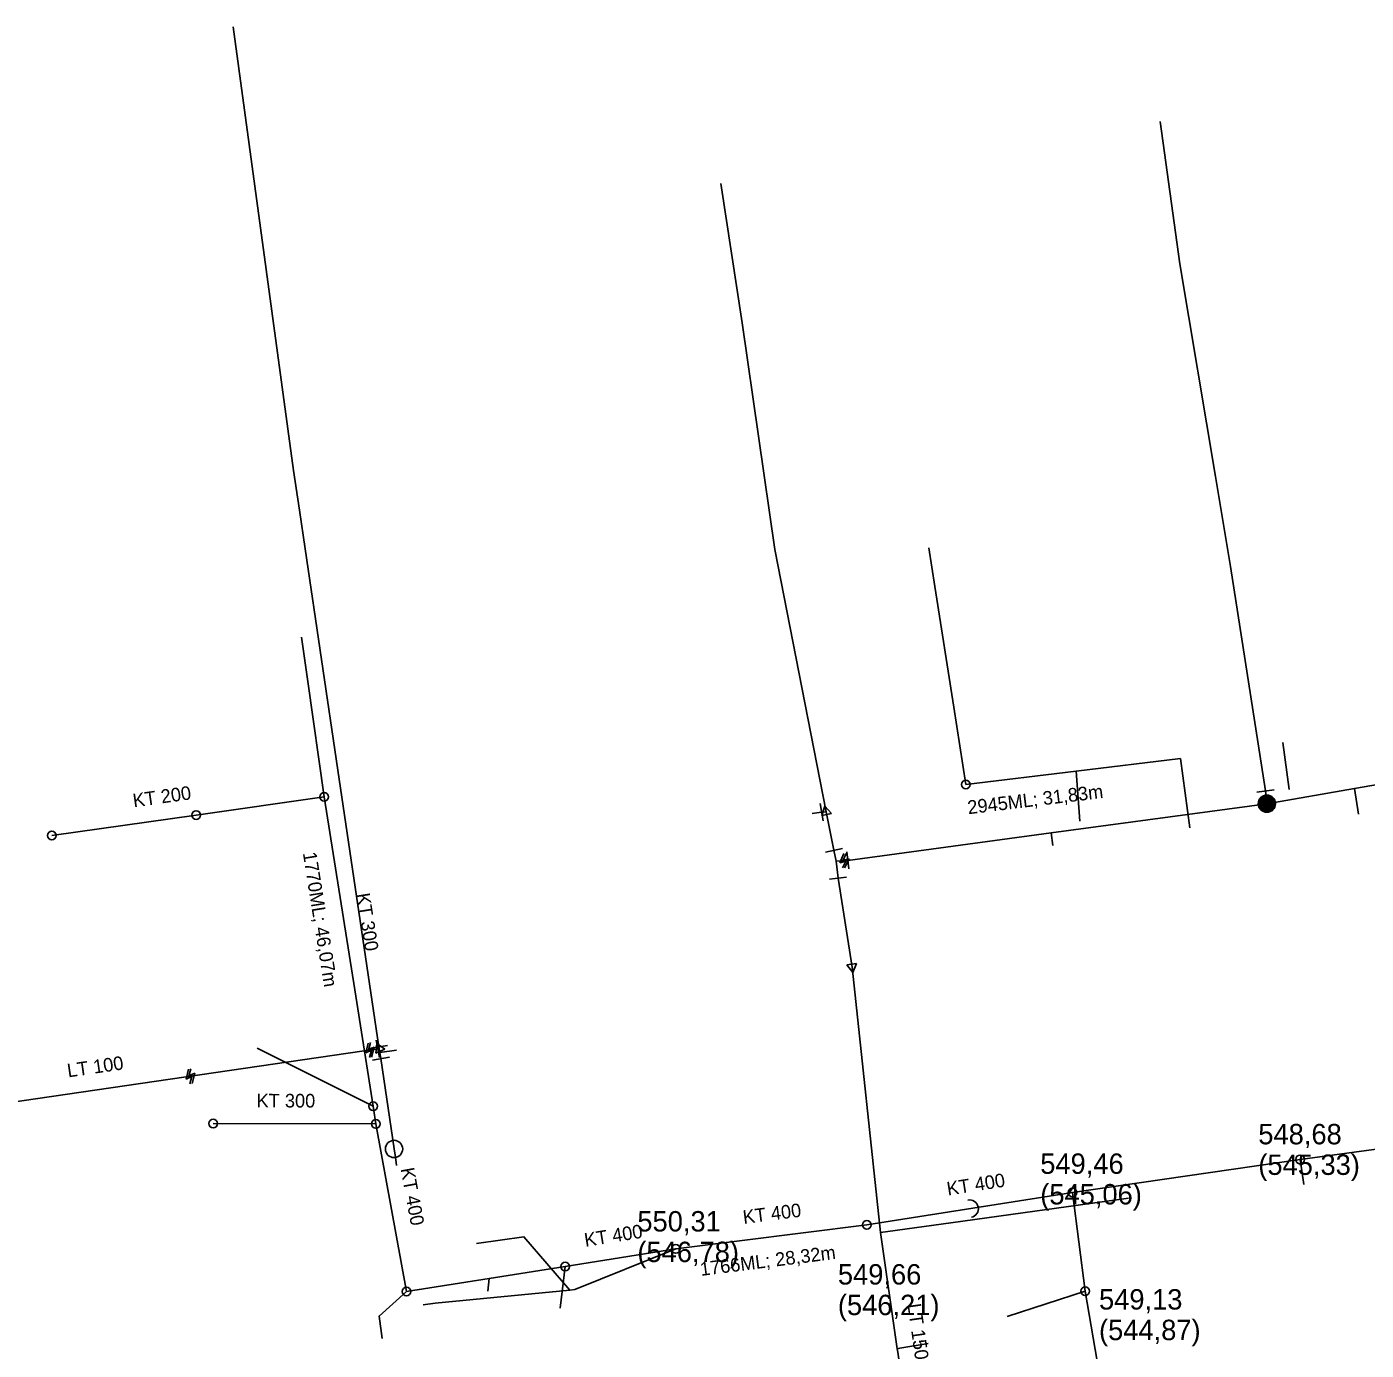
# Model space of a CAD drawing. Extents: x -867696 to -865033, y -1042522 to -1039817.
# Drawn here: x -866337.2 to -866140.2, y -1040061.2 to -1039866.6 of the extents above; entities that cross this region are included whole.
import ezdxf

# ---------------------------------------------------------------- set-up
doc = ezdxf.new("R2010")
doc.units = 0
for name, color, linetype in [('KN - jednotna', 7, 'Continuous'), ('KN - ostatni', 7, 'Continuous'), ('KN - popis material', 7, 'Continuous'), ('KN - popis ostatni', 7, 'Continuous'), ('KN - popis usek delka', 7, 'Continuous'), ('KN - pripojka', 7, 'Continuous'), ('KN - sachta komora', 7, 'Continuous'), ('Level 1', 7, 'Continuous'), ('V - armatura', 7, 'Continuous'), ('V - hydrant', 7, 'Continuous'), ('V - ostatni', 7, 'Continuous'), ('V - popis material', 7, 'Continuous'), ('V - pripojka', 7, 'Continuous'), ('V - rozvadeci', 7, 'Continuous'), ('V - sachta', 7, 'Continuous')]:
    doc.layers.add(name, color=color, linetype=linetype)

# ---------------------------------------------------------------- blocks, each defined once
blk = doc.blocks.new('100.M')
at = {"layer": 'Level 1'}
blk.add_circle((0, 0), 1.27, dxfattribs=at)
blk = doc.blocks.new('107')
at = {"layer": 'Level 1'}
blk.add_arc((0, 0), 1.27, 270, 90, dxfattribs=at)
blk = doc.blocks.new('111')
at = {"layer": 'Level 1'}
for p, q in [((0.42, 0.72), (-0.83, 0)), ((-0.83, 0), (0.42, -0.72)), ((0.42, -0.72), (0.42, 0.72))]:
    blk.add_line(p, q, dxfattribs=at)
blk = doc.blocks.new('147')
at = {"layer": 'Level 1'}
blk.add_line((0, 1.27), (0, -1.27), dxfattribs=at)
blk = doc.blocks.new('160')
at = {"layer": 'Level 1'}
for p, q in [((-1.26, -0.04), (0.05, 1.27)), ((-1.26, -0.06), (0.06, 1.27)), ((-1.26, -0.07), (0.08, 1.27)), ((-1.26, -0.09), (0.09, 1.27)), ((-1.26, 0.11), (-0.12, 1.26)), ((-1.26, 0.1), (-0.1, 1.26)), ((-1.26, 0.08), (-0.09, 1.26)), ((-1.26, 0.07), (-0.07, 1.26)), ((-1.26, 0.06), (-0.06, 1.26)), ((-1.26, 0.04), (-0.04, 1.26)), ((-1.26, 0.03), (-0.03, 1.26)), ((-1.26, 0.01), (-0.01, 1.26)), ((-1.26, 0), (0, 1.26)), ((-1.26, -0.02), (0.02, 1.26)), ((-1.26, -0.03), (0.03, 1.26)), ((-1.26, -0.1), (0.1, 1.26)), ((-1.26, -0.11), (0.12, 1.26)), ((-1.26, -0.13), (0.13, 1.26)), ((-1.26, -0.14), (0.14, 1.26)), ((-1.26, 0.17), (-0.18, 1.25)), ((-1.26, 0.15), (-0.16, 1.25)), ((-1.26, 0.14), (-0.15, 1.25)), ((-1.26, 0.13), (-0.13, 1.25)), ((-1.26, -0.16), (0.15, 1.25)), ((-1.26, -0.17), (0.16, 1.25)), ((-1.25, 0.21), (-0.21, 1.25)), ((-1.25, 0.19), (-0.19, 1.25)), ((-1.25, -0.18), (0.17, 1.25)), ((-1.25, -0.19), (0.19, 1.25)), ((-1.25, -0.2), (0.2, 1.24)), ((-1.25, -0.21), (0.21, 1.24)), ((-1.24, 0.25), (-0.24, 1.25)), ((-1.24, 0.23), (-0.22, 1.25)), ((-1.24, -0.22), (0.22, 1.24)), ((-1.24, -0.24), (0.23, 1.24)), ((-1.24, -0.25), (0.25, 1.24)), ((-1.23, 0.27), (-0.26, 1.24)), ((-1.23, 0.29), (-0.28, 1.23)), ((-1.23, -0.26), (0.26, 1.23)), ((-1.23, -0.27), (0.27, 1.23)), ((-1.23, -0.28), (0.28, 1.23)), ((-1.23, -0.29), (0.29, 1.23)), ((-1.22, 0.3), (-0.3, 1.23)), ((-1.22, 0.32), (-0.32, 1.22)), ((-1.22, -0.3), (0.31, 1.22)), ((-1.22, -0.32), (0.32, 1.22)), ((-1.22, -0.33), (0.33, 1.22)), ((-1.21, -0.34), (0.34, 1.22)), ((-1.21, -0.35), (0.35, 1.22)), ((-1.21, 0.36), (-0.36, 1.21)), ((-1.21, 0.34), (-0.34, 1.21)), ((-1.21, -0.36), (0.36, 1.21)), ((-1.21, -0.37), (0.38, 1.21)), ((-1.2, -0.38), (0.39, 1.21)), ((-1.2, 0.38), (-0.38, 1.2)), ((-1.2, -0.39), (0.4, 1.2)), ((-1.2, -0.41), (0.41, 1.2)), ((-1.2, 0.4), (-0.4, 1.19)), ((-1.19, -0.42), (0.42, 1.2)), ((-1.19, 0.42), (-0.43, 1.19)), ((-1.19, -0.43), (0.43, 1.19)), ((-1.19, -0.44), (0.44, 1.19)), ((-1.19, 0.44), (-0.45, 1.18)), ((-1.19, -0.45), (0.45, 1.18)), ((-1.18, -0.46), (0.46, 1.18)), ((-1.18, 0.46), (-0.47, 1.17)), ((-1.18, -0.47), (0.47, 1.17)), ((-1.17, 0.48), (-0.49, 1.17)), ((-1.17, -0.48), (0.48, 1.17)), ((-1.17, -0.49), (0.49, 1.16)), ((-1.16, 0.51), (-0.51, 1.16)), ((-1.16, -0.5), (0.5, 1.16)), ((-1.16, -0.51), (0.5, 1.16)), ((-1.15, -0.52), (0.51, 1.15)), ((-1.15, -0.53), (0.52, 1.15)), ((-1.14, 0.54), (-0.53, 1.15)), ((-1.14, -0.54), (0.53, 1.14)), ((-1.14, -0.54), (0.54, 1.14)), ((-1.13, -0.55), (0.55, 1.13)), ((-1.13, -0.56), (0.56, 1.13)), ((-1.12, 0.58), (-0.56, 1.14)), ((-1.12, -0.57), (0.57, 1.12)), ((-1.12, -0.58), (0.58, 1.12)), ((-1.11, -0.59), (0.59, 1.11)), ((-1.11, -0.6), (0.6, 1.11)), ((-1.1, 0.61), (-0.6, 1.11)), ((-1.1, -0.61), (0.61, 1.11)), ((-1.1, -0.62), (0.62, 1.1)), ((-1.09, -0.63), (0.63, 1.1)), ((-1.09, 0.64), (-0.64, 1.09)), ((-1.09, -0.64), (0.64, 1.09)), ((-1.08, -0.65), (0.65, 1.09)), ((-1.08, -0.65), (0.66, 1.08)), ((-1.07, -0.66), (0.67, 1.08)), ((-1.07, -0.67), (0.68, 1.07)), ((-1.07, 0.67), (-0.68, 1.06)), ((-1.06, -0.68), (0.69, 1.07)), ((-1.06, -0.69), (0.69, 1.06)), ((-1.05, -0.7), (0.7, 1.05)), ((-1.05, -0.71), (0.71, 1.05)), ((-1.05, 0.7), (-0.71, 1.04)), ((-1.04, -0.72), (0.72, 1.04)), ((-1.04, -0.73), (0.72, 1.04)), ((-1.03, -0.74), (0.73, 1.03)), ((-1.03, -0.75), (0.74, 1.02)), ((-1.03, 0.73), (-0.75, 1.01)), ((-1.02, -0.75), (0.75, 1.02)), ((-1.01, -0.76), (0.76, 1.01)), ((-1.01, -0.77), (0.76, 1)), ((-1, -0.77), (0.77, 1)), ((-0.99, -0.78), (0.78, 0.99)), ((-0.99, -0.79), (0.79, 0.98)), ((-0.98, -0.8), (0.79, 0.98)), ((-0.97, -0.8), (0.8, 0.97)), ((-0.97, -0.81), (0.81, 0.97)), ((-0.96, -0.82), (0.82, 0.96)), ((-0.95, -0.83), (0.83, 0.95)), ((-0.95, -0.83), (0.83, 0.95)), ((-0.94, -0.84), (0.84, 0.94)), ((-0.93, -0.85), (0.85, 0.93)), ((-0.93, -0.86), (0.86, 0.93)), ((-0.92, -0.86), (0.86, 0.92)), ((-0.91, 0.87), (-0.79, 0.99)), ((-0.91, -0.87), (0.87, 0.91)), ((-0.91, -0.88), (0.88, 0.91)), ((-0.9, -0.88), (0.89, 0.9)), ((-0.89, -0.89), (0.89, 0.89)), ((-0.88, -0.9), (0.9, 0.89)), ((-0.88, -0.91), (0.91, 0.88)), ((-0.87, -0.91), (0.92, 0.88)), ((-0.86, -0.92), (0.93, 0.87)), ((-0.86, -0.93), (0.93, 0.86)), ((-0.85, -0.94), (0.94, 0.85)), ((-0.84, -0.94), (0.94, 0.84)), ((-0.84, -0.95), (0.95, 0.84)), ((-0.83, -0.96), (0.96, 0.83)), ((-0.82, -0.96), (0.96, 0.82)), ((-0.82, -0.97), (0.97, 0.81)), ((-0.81, -0.98), (0.97, 0.8)), ((-0.8, -0.98), (0.98, 0.8)), ((-0.79, -0.99), (0.99, 0.79)), ((-0.78, -1), (0.99, 0.78)), ((-0.77, -1), (1, 0.77)), ((-0.77, -1.01), (1, 0.76)), ((-0.76, -1.01), (1.01, 0.75)), ((-0.75, -1.02), (1.02, 0.75)), ((-0.74, -1.02), (1.02, 0.74)), ((-0.73, -1.03), (1.03, 0.73)), ((-0.72, -1.03), (1.03, 0.72)), ((-0.71, -1.04), (1.04, 0.71)), ((-0.71, -1.04), (1.04, 0.71)), ((-0.7, -1.05), (1.05, 0.7)), ((-0.69, -1.06), (1.06, 0.69)), ((-0.68, -1.06), (1.06, 0.68)), ((-0.67, -1.07), (1.07, 0.67)), ((-0.66, -1.07), (1.07, 0.66)), ((-0.65, -1.08), (1.08, 0.66)), ((-0.64, -1.08), (1.09, 0.65)), ((-0.64, -1.09), (1.09, 0.64)), ((-0.63, -1.09), (1.1, 0.63)), ((-0.62, -1.1), (1.1, 0.62)), ((-0.61, -1.11), (1.11, 0.62)), ((-0.6, -1.11), (1.12, 0.61)), ((-0.59, -1.12), (1.12, 0.6)), ((-0.58, -1.12), (1.12, 0.59)), ((-0.58, -1.13), (1.13, 0.58)), ((-0.57, -1.13), (1.13, 0.57)), ((-0.56, -1.14), (1.14, 0.56)), ((-0.55, -1.14), (1.14, 0.55)), ((-0.54, -1.15), (1.14, 0.54)), ((-0.53, -1.15), (1.15, 0.52)), ((-0.52, -1.16), (1.15, 0.51)), ((-0.51, -1.16), (1.16, 0.5)), ((-0.5, -1.16), (1.16, 0.49)), ((-0.49, -1.17), (1.16, 0.48)), ((-0.48, -1.17), (1.17, 0.47)), ((-0.47, -1.17), (1.17, 0.46)), ((-0.46, -1.18), (1.18, 0.45)), ((-0.44, -1.18), (1.18, 0.44)), ((-0.43, -1.18), (1.18, 0.43)), ((-0.42, -1.19), (1.19, 0.42)), ((-0.41, -1.19), (1.19, 0.41)), ((-0.4, -1.19), (1.2, 0.4)), ((-0.39, -1.2), (1.2, 0.39)), ((-0.38, -1.2), (1.2, 0.38)), ((-0.37, -1.2), (1.21, 0.37)), ((-0.36, -1.21), (1.21, 0.36)), ((-0.35, -1.21), (1.22, 0.35)), ((-0.34, -1.22), (1.22, 0.34)), ((-0.33, -1.22), (1.22, 0.33)), ((-0.32, -1.22), (1.23, 0.32)), ((-0.31, -1.23), (1.23, 0.31)), ((-0.3, -1.23), (1.23, 0.3)), ((-0.28, -1.23), (1.23, 0.29)), ((-0.27, -1.24), (1.24, 0.27)), ((-0.26, -1.24), (1.24, 0.26)), ((-0.25, -1.24), (1.24, 0.25)), ((-0.24, -1.25), (1.24, 0.24)), ((-0.23, -1.25), (1.24, 0.22)), ((-0.22, -1.25), (1.24, 0.21)), ((-0.2, -1.25), (1.24, 0.2)), ((-0.19, -1.25), (1.25, 0.19)), ((-0.18, -1.25), (1.25, 0.17)), ((-0.16, -1.25), (1.25, 0.16)), ((-0.15, -1.25), (1.25, 0.15)), ((-0.14, -1.25), (1.25, 0.14)), ((-0.12, -1.25), (1.25, 0.12)), ((-0.11, -1.26), (1.26, 0.11)), ((-0.1, -1.26), (1.26, 0.1)), ((-0.08, -1.26), (1.26, 0.09)), ((-0.07, -1.26), (1.26, 0.07)), ((-0.06, -1.26), (1.26, 0.06)), ((-0.04, -1.26), (1.26, 0.05)), ((-0.03, -1.26), (1.27, 0.04)), ((-0.02, -1.26), (1.27, 0.02)), ((0, -1.26), (1.27, 0.01)), ((0.01, -1.26), (1.27, 0)), ((0.02, -1.26), (1.27, -0.02)), ((0.04, -1.27), (1.27, -0.04)), ((0.05, -1.27), (1.26, -0.05)), ((0.06, -1.27), (1.26, -0.07)), ((0.08, -1.27), (1.26, -0.08)), ((0.09, -1.26), (1.26, -0.1)), ((0.11, -1.26), (1.26, -0.12)), ((0.13, -1.26), (1.25, -0.13)), ((0.15, -1.25), (1.25, -0.15)), ((0.16, -1.25), (1.25, -0.17)), ((0.18, -1.25), (1.25, -0.18)), ((0.2, -1.24), (1.24, -0.2)), ((0.22, -1.24), (1.24, -0.21)), ((0.23, -1.24), (1.24, -0.23)), ((0.25, -1.24), (1.24, -0.25)), ((0.27, -1.23), (1.24, -0.26)), ((0.28, -1.23), (1.23, -0.28)), ((0.3, -1.23), (1.23, -0.3)), ((0.32, -1.22), (1.23, -0.31)), ((0.34, -1.22), (1.22, -0.33)), ((0.35, -1.22), (1.22, -0.35)), ((0.37, -1.21), (1.21, -0.38)), ((0.39, -1.21), (1.2, -0.4)), ((0.42, -1.2), (1.19, -0.43)), ((0.44, -1.18), (1.18, -0.45)), ((0.47, -1.17), (1.17, -0.47)), ((0.5, -1.16), (1.16, -0.5)), ((0.52, -1.15), (1.15, -0.52)), ((0.55, -1.13), (1.14, -0.54)), ((0.58, -1.12), (1.13, -0.57)), ((0.6, -1.11), (1.12, -0.59)), ((0.63, -1.1), (1.11, -0.61)), ((0.65, -1.09), (1.08, -0.66)), ((0.69, -1.06), (1.04, -0.72)), ((0.77, -1), (1, -0.77)), ((0.85, -0.93), (0.96, -0.82))]:
    blk.add_line(p, q, dxfattribs=at)
blk.add_circle((0, 0), 1.27, dxfattribs=at)
blk = doc.blocks.new('143')
at = {"layer": 'Level 1'}
blk.add_circle((0, 0), 1.27, dxfattribs=at)
blk = doc.blocks.new('156')
at = {"layer": 'Level 1'}
for p, q in [((-0.07, 1.04), (-0.68, -0.3)), ((0.28, 1.04), (-0.19, 0.08)), ((-0.19, 0.08), (0.7, 0.29)), ((0.7, 0.29), (0.02, -1.08)), ((-0.68, -0.3), (0.21, -0.09)), ((0.21, -0.09), (-0.28, -1.08))]:
    blk.add_line(p, q, dxfattribs=at)
blk = doc.blocks.new('150')
at = {"layer": 'Level 1'}
blk.add_line((0, 1.27), (0, -1.27), dxfattribs=at)

msp = doc.modelspace()

# ---------------------------------------------------------------- linework, layer by layer
at = {"layer": 'KN - jednotna'}
for points in [[(-866204.548, -1039943.223), (-866203.66, -1039948.888), (-866200.873, -1039966.661), (-866199.093, -1039978.013)], [(-866293.448, -1039979.846), (-866295.843, -1039962.848), (-866296.762, -1039956.329)], [(-866199.093, -1039978.013), (-866182.862, -1039976.046), (-866167.497, -1039974.183)], [(-866293.448, -1039979.846), (-866312.287, -1039982.514)], [(-866286.259, -1040025.353), (-866288.936, -1040008.219), (-866293.448, -1039979.846)], [(-866312.287, -1039982.514), (-866333.509, -1039985.52)], [(-866285.862, -1040027.954), (-866285.961, -1040027.282), (-866286.259, -1040025.353)], [(-866285.862, -1040027.954), (-866309.765, -1040027.901)], [(-866281.35, -1040052.61), (-866285.862, -1040027.954)], [(-866149.932, -1040033.166), (-866139.087, -1040031.706), (-866121.369, -1040029.322), (-866117.694, -1040028.827)], [(-866183.4, -1040038.039), (-866149.932, -1040033.166)], [(-866183.4, -1040038.039), (-866213.65, -1040042.794)], [(-866181.549, -1040052.562), (-866183.4, -1040038.039)], [(-866213.65, -1040042.794), (-866241.75, -1040046.34)], [(-866241.75, -1040046.34), (-866258.017, -1040048.94)], [(-866258.017, -1040048.94), (-866269.168, -1040050.694), (-866281.35, -1040052.61)], [(-866177.737, -1040074.575), (-866181.549, -1040052.562)]]:
    msp.add_lwpolyline(points, dxfattribs=at)
at = {"layer": 'KN - pripojka'}
for points in [[(-866152.458, -1039971.822), (-866151.519, -1039978.764)], [(-866167.497, -1039974.183), (-866166.133, -1039984.379)], [(-866182.862, -1039976.046), (-866182.335, -1039983.433)], [(-866286.259, -1040025.353), (-866303.32, -1040016.817)], [(-866149.932, -1040033.166), (-866149.383, -1040036.879)], [(-866241.75, -1040046.34), (-866256.6, -1040052.31), (-866257.32, -1040052.42), (-866264.08, -1040044.54), (-866271.06, -1040045.55)], [(-866269.168, -1040050.694), (-866269.378, -1040052.57)], [(-866258.017, -1040048.94), (-866258.756, -1040055.038)], [(-866281.35, -1040052.61), (-866285.37, -1040056.21), (-866284.92, -1040059.52)], [(-866257.32, -1040052.42), (-866277.13, -1040054.3), (-866278.88, -1040054.57)], [(-866181.549, -1040052.562), (-866193.008, -1040056.254)]]:
    msp.add_lwpolyline(points, dxfattribs=at)
at = {"layer": 'V - pripojka'}
for points in [[(-866141.906, -1039978.607), (-866141.322, -1039982.358)], [(-866219.646, -1039982.032), (-866220.29, -1039982.091), (-866221.672, -1039982.289)], [(-866186.553, -1039985.133), (-866186.29, -1039986.979)], [(-866285.261, -1040017.45), (-866282.836, -1040017.098)], [(-866283.175, -1040031.63), (-866282.978, -1040032.854), (-866282.801, -1040034.044)], [(-866211.61, -1040043.912), (-866210.548, -1040043.764), (-866201.274, -1040042.475), (-866175.187, -1040038.847)], [(-866209.17, -1040061.029), (-866208.798, -1040060.951), (-866204.637, -1040060.246)]]:
    msp.add_lwpolyline(points, dxfattribs=at)
at = {"layer": 'V - rozvadeci'}
for points in [[(-866306.826, -1039866.558), (-866297.95, -1039931.853), (-866297.089, -1039937.682), (-866296.249, -1039943.374), (-866291.446, -1039975.893), (-866285.393, -1040016.616)], [(-866170.484, -1039880.502), (-866167.595, -1039901.431), (-866162.367, -1039932.688), (-866160.148, -1039945.952), (-866155.016, -1039978.961)], [(-866219.646, -1039982.032), (-866227.167, -1039943.427), (-866231.992, -1039910.103), (-866235.131, -1039889.597)], [(-866090.65, -1039969.748), (-866141.906, -1039978.607), (-866154.816, -1039980.838)], [(-866155.016, -1039978.961), (-866154.816, -1039980.838)], [(-866216.431, -1039989.176), (-866186.553, -1039985.133), (-866154.816, -1039980.838)], [(-866218.476, -1039987.69), (-866219.646, -1039982.032)], [(-866218.142, -1039989.308), (-866218.476, -1039987.69)], [(-866218.142, -1039989.308), (-866216.431, -1039989.176)], [(-866217.879, -1039991.809), (-866218.142, -1039989.308)], [(-866215.797, -1040004.868), (-866217.879, -1039991.809)], [(-866197.455, -1040117.928), (-866202.847, -1040105.383), (-866206.328, -1040080.964), (-866209.102, -1040061.504), (-866209.17, -1040061.029), (-866211.61, -1040043.912), (-866215.797, -1040004.868)], [(-866364.138, -1040028.354), (-866285.566, -1040016.9)], [(-866285.566, -1040016.9), (-866285.356, -1040016.87)], [(-866285.393, -1040016.616), (-866285.356, -1040016.87)], [(-866285.356, -1040016.87), (-866285.261, -1040017.45)], [(-866285.261, -1040017.45), (-866285.102, -1040018.326)], [(-866285.102, -1040018.326), (-866283.175, -1040031.63)]]:
    msp.add_lwpolyline(points, dxfattribs=at)

# ---------------------------------------------------------------- block references
at = {"layer": 'KN - ostatni', "xscale": 1.008377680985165, "yscale": 1.0083776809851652, "rotation": 11.626378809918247}
msp.add_blockref('107', (-866198.525, -1040040.416), dxfattribs=at)
at = {"layer": 'KN - sachta komora'}
for p, xscale, yscale, rotation in [((-866199.093, -1039978.013), 0.49999999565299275, 0.4999999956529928, 142.99999806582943), ((-866293.448, -1039979.846), 0.5000000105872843, 0.5000000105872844, -81.00000039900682), ((-866312.287, -1039982.514), 0.5041888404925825, 0.5041888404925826, 11.626378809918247), ((-866333.509, -1039985.52), 0.5041888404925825, 0.5041888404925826, -168.37362119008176), ((-866286.259, -1040025.353), 0.5000000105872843, 0.5000000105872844, -81.00000039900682), ((-866309.765, -1040027.901), 0.5, 0.5, 180), ((-866285.862, -1040027.954), 0.49999998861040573, 0.4999999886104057, -79.99999971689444), ((-866149.932, -1040033.166), 0.5046025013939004, 0.5046025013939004, -168.88308178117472), ((-866183.4, -1040038.039), 0.5000000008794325, 0.5000000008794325, 144.00000066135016), ((-866213.65, -1040042.794), 0.5041888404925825, 0.5041888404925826, 11.626378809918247), ((-866241.75, -1040046.34), 0.5041888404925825, 0.5041888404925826, 11.626378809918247), ((-866258.017, -1040048.94), 0.5036654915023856, 0.5036654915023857, 12.13890866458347), ((-866281.35, -1040052.61), 0.5000000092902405, 0.5000000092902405, -35.000000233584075), ((-866181.549, -1040052.562), 0.5000000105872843, 0.5000000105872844, 98.99999960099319)]:
    msp.add_blockref('100.M', p, dxfattribs=dict(at, xscale=xscale, yscale=yscale, rotation=rotation))
at = {"layer": 'V - armatura'}
for p, xscale, yscale, rotation in [((-866155.016, -1039978.961), 0.9999999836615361, 0.9999999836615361, -81.99999961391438), ((-866218.476, -1039987.69), 1.0000000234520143, 1.0000000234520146, -78.0000006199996), ((-866216.431, -1039989.176), 1.0011217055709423, 1.0011217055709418, -173.41739016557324), ((-866217.879, -1039991.809), 1.000191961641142, 1.000191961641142, 97.08900113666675), ((-866285.393, -1040016.616), 1.0000000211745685, 1.0000000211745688, -81.00000039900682), ((-866285.566, -1040016.9), 1.008377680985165, 1.0083776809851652, 11.626378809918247), ((-866285.102, -1040018.326), 0.9999999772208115, 0.9999999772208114, -79.99999971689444)]:
    msp.add_blockref('147', p, dxfattribs=dict(at, xscale=xscale, yscale=yscale, rotation=rotation))
at = {"layer": 'V - hydrant', "xscale": 1.0098116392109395, "yscale": 1.0098116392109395, "rotation": -169.38969821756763}
msp.add_blockref('150', (-866220.29, -1039982.091), dxfattribs=at)
at = {"layer": 'V - ostatni', "rotation": 180}
msp.add_blockref('160', (-866154.816, -1039980.838), dxfattribs=at)
at = {"layer": 'V - ostatni'}
for name, p, xscale, yscale, rotation in [('111', (-866219.646, -1039982.032), 1.0000000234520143, 1.0000000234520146, -78.0000006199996), ('111', (-866215.797, -1040004.868), 0.9999999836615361, 0.9999999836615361, 98.00000038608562), ('156', (-866286.715, -1040017.068), 1.008377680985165, 1.0083776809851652, 11.626378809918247), ('111', (-866285.356, -1040016.87), 1.000000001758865, 1.000000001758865, 54.00000066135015), ('156', (-866313.125, -1040020.918), 1.008377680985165, 1.0083776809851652, 11.626378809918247)]:
    msp.add_blockref(name, p, dxfattribs=dict(at, xscale=xscale, yscale=yscale, rotation=rotation))
msp.add_blockref('156', (-866216.94, -1039989.22), dxfattribs=at)
at = {"layer": 'V - sachta', "xscale": 1.0000000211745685, "yscale": 1.0000000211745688, "rotation": -81.00000039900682}
msp.add_blockref('143', (-866283.175, -1040031.63), dxfattribs=at)

# ---------------------------------------------------------------- texts
at = {"layer": 'KN - popis material'}
for s, rotation, p in [('KT 200', 8.06, (-866321.446, -1039981.387)), ('KT 300', 279.04, (-866288.745, -1039994.137)), ('KT 300', 359.87, (-866303.388, -1040025.515)), ('KT 400', 280.37, (-866282.215, -1040034.553)), ('KT 400', 8.93, (-866201.723, -1040038.489)), ('KT 400', 7.19, (-866231.753, -1040042.659)), ('KT 400', 9.08, (-866255.028, -1040046.031))]:
    msp.add_text(s, height=2, rotation=rotation, dxfattribs=at).set_placement(p)
at = {"layer": 'KN - popis ostatni'}
for s, p in [('548,68 ', (-866156.072, -1040030.946)), ('549,46 ', (-866188.14, -1040035.289)), ('(545,33)', (-866156.072, -1040035.446)), ('(545,06)', (-866188.14, -1040039.789)), ('550,31 ', (-866247.39, -1040043.77)), ('(546,78)', (-866247.39, -1040048.27)), ('549,66 ', (-866217.9, -1040051.574)), ('549,13 ', (-866179.499, -1040055.252)), ('(546,21)', (-866217.9, -1040056.074)), ('(544,87)', (-866179.499, -1040059.752))]:
    msp.add_text(s, height=3, dxfattribs=at).set_placement(p)
at = {"layer": 'KN - popis usek delka'}
for s, rotation, p in [('2945ML; 31,83m', 6.91, (-866198.717, -1039982.399)), ('1770ML; 46,07m', 279.04, (-866296.592, -1039988.096)), ('1766ML; 28,32m', 7.19, (-866238.045, -1040050.306))]:
    msp.add_text(s, height=1.99999, rotation=rotation, dxfattribs=at).set_placement(p)
at = {"layer": 'V - popis material'}
for s, rotation, p in [('LT 100', 8.29, (-866331.096, -1040021.112)), ('LT 150', 278.11, (-866207.676, -1040054.505))]:
    msp.add_text(s, height=2, rotation=rotation, dxfattribs=at).set_placement(p)

doc.saveas('drawing.dxf')
